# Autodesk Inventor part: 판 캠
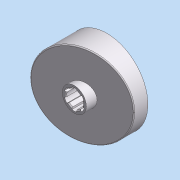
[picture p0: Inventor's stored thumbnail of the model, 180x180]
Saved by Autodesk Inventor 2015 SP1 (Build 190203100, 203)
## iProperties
Created: 2012-05
Part Number: 판 캠
Document SubType Name: 모델링
Designer: SeoGD™
Material: 일반
Appearance: 알루미늄 - 평지
Mass: 86.8264 g
Surface Area: 331.303 cm^2
Volume: 86.8264 cm^3
Density: 1 g/cm^3
변환 표준: STEP AP214IS
파일 이름: C:\Users\SeoGD\Desktop\?쒗뿕\??stp
전처리기: Build: 253, Release: 2010 SP1 - Date: Wed 07/29/2009
전송 단위: 밀리미터
불확실성: 0.01
Author: SeoGD™
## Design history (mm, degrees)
node "작업 평면4"
sketch "스케치1"
  geometry: C1 r 44.5 at (0, 0); 1 further point
  constraints: 1 centre point, 1 coincident
  dimensions: "d25" = 89 diameter of C1
extrude "돌출1" new body sketch "스케치1" distance "d1" = 40; taper "d2" = 0 deg
sketch "스케치2"
  geometry: L1 (-44.5, 15)-(44.5, 38.847); L2 (-44.5, 0)-(-44.5, 40) reference; L3 (-44.5, 40)-(44.5, 40) reference; L4 (44.5, 0)-(44.5, 40) reference; 1 further point
  constraints: 2 end point, 2 point on line
  dimensions: "d26" = 15 distance of L2.start L1.start; "d27" = 75 deg angle of L1 L2
extrude "돌출2" cut sketch "스케치2" stored distance "d5" = 40; taper "d6" = 0 deg
node "작업 평면1"
sketch "스케치3"
  geometry: C1 r 13 at (0, 0); 1 further point
  constraints: 1 centre point, 1 coincident
  dimensions: "d9" = 26 diameter of C1
extrude "돌출3" join sketch "스케치3" distance "d10" = 38; taper "d11" = 0 deg
hole "구멍1" diameter "d14" = 18; stored, may be unused: countersink angle "d18" = 90 deg, drill point angle "d20" = 118 deg; dims "d12" = 10, "d13" = 10, "d15" = 6, "d16" = 4, "d17" = 2, "d19" = 8
feature "쉘2" dims "d29" = 5
sketch "스케치6"
  geometry: C1 r 17.5 at (0, 0); C2 r 14 at (0, 0) reference; 1 further point
  constraints: 1 centre point, 1 coincident
  dimensions: "d28" = 35 diameter of C1
extrude "돌출4" join sketch "스케치6" stored distance "d30" = 38; taper "d31" = 0 deg
fillet "모깎기1" dims "d32" = 3
chamfer "모따기1" distance "d21" = 1; stored, may be unused: second distance "d22" = 2, angle "d23" = 45 deg
sketch "스케치7"
  geometry: L1 (-12.374, 12.374)-(-27.931, 27.931); A1 r 39.5 centre (0, 0) between (-27.931, 27.931) and (0, 39.5) reference; 2 further points
  constraints: 2 end point, 2 point on circle, 1 point on line, 1 vertical alignment, 2 other
  dimensions: "d33" = 45 deg dimension on point (0, 0) L1.start A1.end
feature "리브1" sketch "스케치7" dims "d34" = 5, "d35" = 1, "d36" = 0
fillet "모깎기2" dims "d37" = 3
sketch "스케치8"
  geometry: L1 (2.5, 10.712)-(2.5, 8.646); L2 (-2.5, 10.712)-(-2.5, 8.646); A1 r 11 centre (0, 0) between (2.5, 10.712) and (-2.5, 10.712); A2 r 9 centre (0, 0) between (2.5, 8.646) and (-2.5, 8.646) reference; 1 further point
  constraints: 4 end point, 4 point on circle, 2 parallel, 1 centre point, 1 coincident, 1 vertical
  dimensions: "d41" = 22 diameter of A1; "d42" = 5 distance between parallel lines of L1 L2
extrude "돌출5" cut sketch "스케치8" stored distance "d43" = 38; taper "d44" = 0 deg
fillet "모깎기3" dims "d48" = 1
node "솔리드1"
node "솔리드 본체"
node "곡면 본체"
pattern_circular "원형 패턴1" dims angle "d39" = 360 deg
pattern_circular "원형 패턴2" dims angle "d46" = 360 deg
node "솔리드2"
